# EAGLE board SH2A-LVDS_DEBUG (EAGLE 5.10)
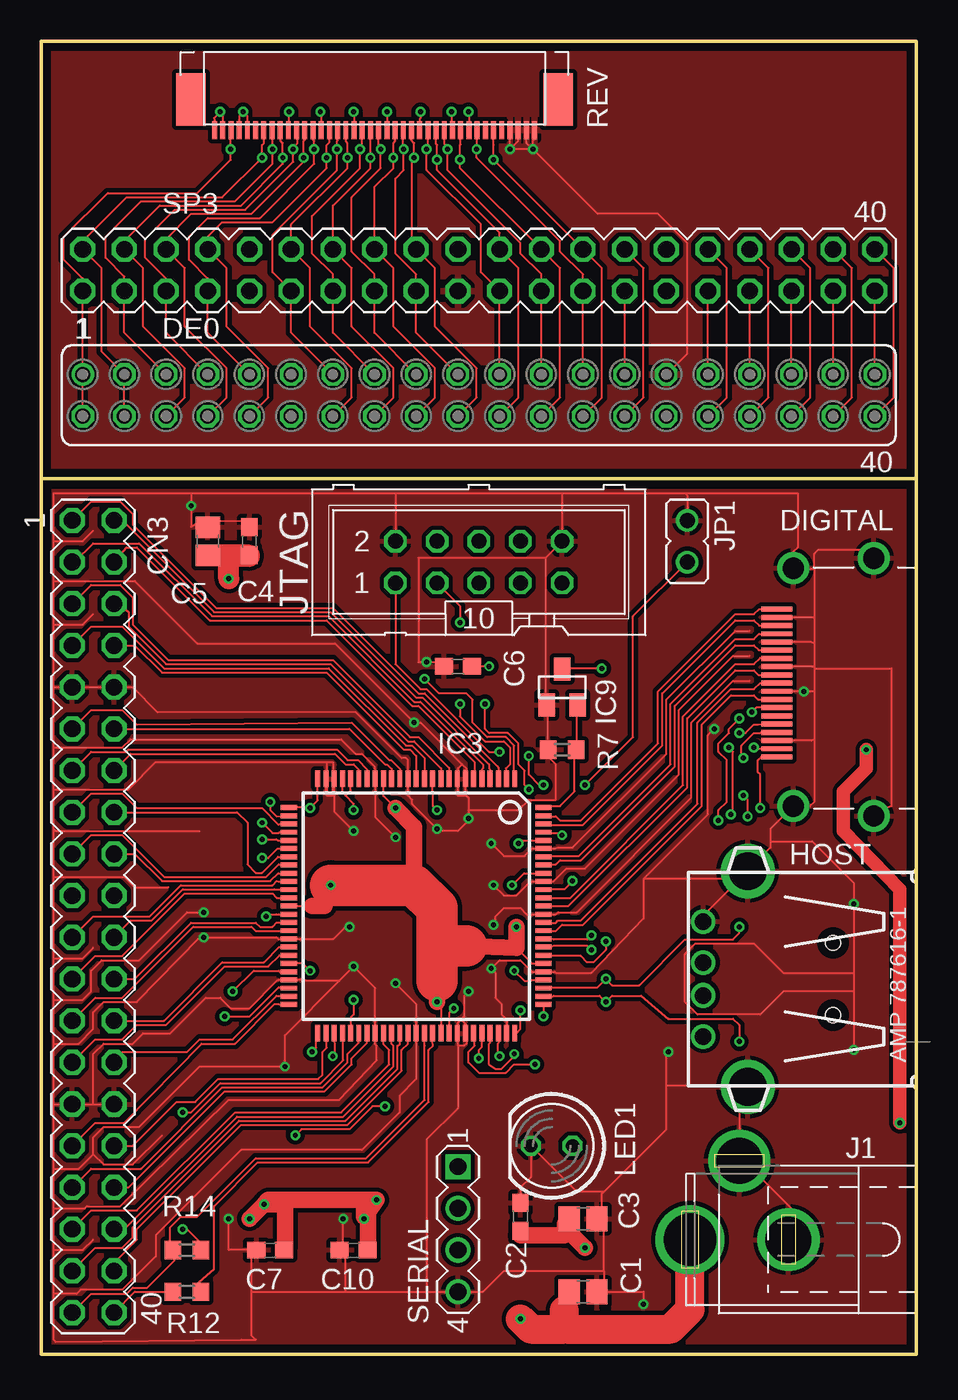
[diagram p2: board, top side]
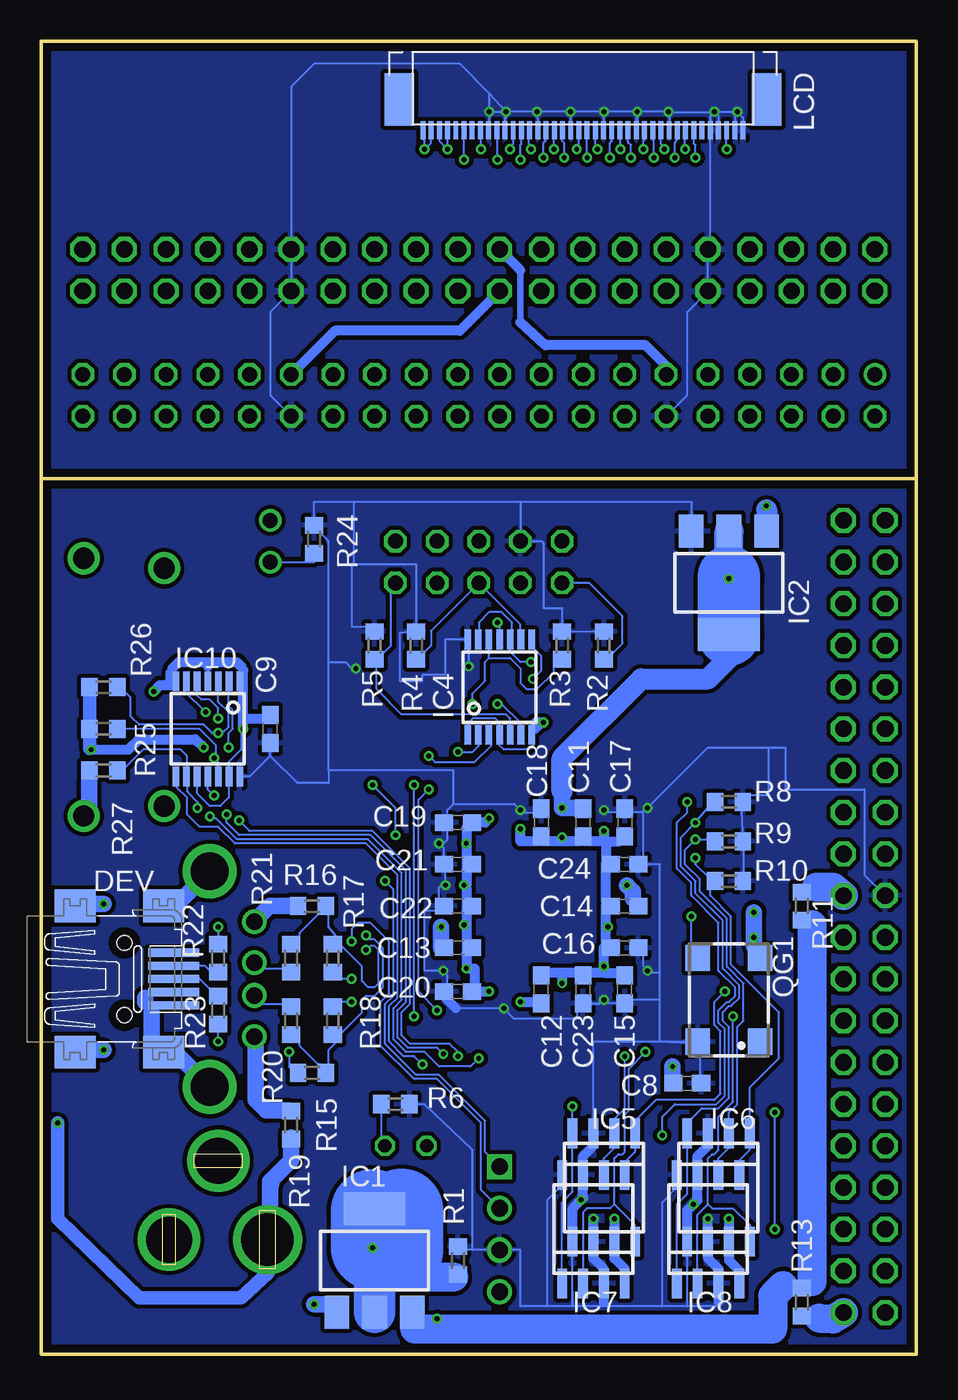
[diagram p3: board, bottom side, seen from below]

Size 53.34 x 80 mm. Coordinates in mm from the lower left corner, seen from the top.
Outline: 0,53.34 0,80 53.34,80 53.34,53.34
Outline: 0,53.34 0,0 53.34,0 53.34,53.34
Outline: 0,53.34 53.34,53.34
Copper layers (1*16): Top 0.035mm / dielectric 1.53mm / Bottom 0.035mm
Design rules "pban_5mil-l2 *": minimum track width 5mil, minimum drill 0.3mm, track to track 5mil, track to pad 0.229mm, pad to pad 5mil, via to via 5mil, smd to smd 5mil, copper to edge 0.5mm, drill to drill 0.5mm, minimum pad ring 0.15mm, minimum via ring 0.15mm, stop-mask expansion 4mil, vias tented up to drill 0.35mm, thermal gap 10mil

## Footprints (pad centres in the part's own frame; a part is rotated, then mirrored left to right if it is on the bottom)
C2012 = smd 1.3 x 1.5: 1 -0.85,0; 2 0.85,0
C1608 = smd 1.1 x 1: 1 -0.85,0; 2 0.85,0
MA20-2 = drill 1.016 octagon: 1 -24.13,-1.27; 2 -24.13,1.27; 3 -21.59,-1.27; 4 -21.59,1.27; 5 -19.05,-1.27; 6 -19.05,1.27; 7 -16.51,-1.27; 8 -16.51,1.27; 9 -13.97,-1.27; 10 -13.97,1.27; 11 -11.43,-1.27; 12 -11.43,1.27; 13 -8.89,-1.27; 14 -8.89,1.27; 15 -6.35,-1.27; 16 -6.35,1.27; 17 -3.81,-1.27; 18 -3.81,1.27; 19 -1.27,-1.27; 20 -1.27,1.27; 21 1.27,-1.27; 22 1.27,1.27; 23 3.81,-1.27; 24 3.81,1.27; 25 6.35,-1.27; 26 6.35,1.27; 27 8.89,-1.27; 28 8.89,1.27; 29 11.43,-1.27; 30 11.43,1.27; 31 13.97,-1.27; 32 13.97,1.27; 33 16.51,-1.27; 34 16.51,1.27; 35 19.05,-1.27; 36 19.05,1.27; 37 21.59,-1.27; 38 21.59,1.27; 39 24.13,-1.27; 40 24.13,1.27
FE20-2 = drill 0.914 round: 1 -24.13,1.27 | drill 0.914 octagon: 2 -24.13,-1.27; 3 -21.59,1.27; 4 -21.59,-1.27; 5 -19.05,1.27; 6 -19.05,-1.27; 7 -16.51,1.27; 8 -16.51,-1.27; 9 -13.97,1.27; 10 -13.97,-1.27; 11 -11.43,1.27; 12 -11.43,-1.27; 13 -8.89,1.27; 14 -8.89,-1.27; 15 -6.35,1.27; 16 -6.35,-1.27; 17 -3.81,1.27; 18 -3.81,-1.27; 19 -1.27,1.27; 20 -1.27,-1.27; 21 1.27,1.27; 22 1.27,-1.27; 23 3.81,1.27; 24 3.81,-1.27; 25 6.35,1.27; 26 6.35,-1.27; 27 8.89,1.27; 28 8.89,-1.27; 29 11.43,1.27; 30 11.43,-1.27; 31 13.97,1.27; 32 13.97,-1.27; 33 16.51,1.27; 34 16.51,-1.27; 35 19.05,1.27; 36 19.05,-1.27; 37 21.59,1.27; 38 21.59,-1.27; 39 24.13,1.27; 40 24.13,-1.27
32005-201A = smd 3.1 x 0.5: 1 3,1.6; 2 3,0.8; 3 3,0; 4 3,-0.8; 5 3,-1.6 | smd 2.5 x 2: M1 -3,-4.45; M2 -3,4.45; M3 2.4,4.45; M4 2.4,-4.45 | hole 0.9: 0,2.2; 0,-2.2
HDMI-FCI-A-UPDATE = smd 0.3 x 1.9: 1 4.75,8.5; 2 4.25,8.5; 3 3.75,8.5; 4 3.25,8.5; 5 2.75,8.5; 6 2.25,8.5; 7 1.75,8.5; 8 1.25,8.5; 9 0.75,8.5; 10 0.25,8.5; 11 -0.25,8.5; 12 -0.75,8.5; 13 -1.25,8.5; 14 -1.75,8.5; 15 -2.25,8.5; 16 -2.75,8.5; 17 -3.25,8.5; 18 -3.75,8.5; 19 -4.25,8.5 | drill 1.3 round: 20 -7.85,2.6; 21 7.85,2.6; 22 -7.25,7.5; 23 7.25,7.5
USB = drill 1 round: 1 -3.5,12.99; 2 -1,12.99; 3 1,12.99; 4 3.5,12.99 | drill 2.3 round: P$1 -6.57,10.28; P$2 6.57,10.28
SOT223 = smd 1.5 x 2: 1 -2.3,-3.15; 2 0,-3.15; 3 2.3,-3.15 | smd 3.8 x 2: 4 0,3.15
VQ100 = smd 1 x 0.3: 1 -7.75,6; 2 -7.75,5.5; 3 -7.75,5; 4 -7.75,4.5; 5 -7.75,4; 6 -7.75,3.5; 7 -7.75,3; 8 -7.75,2.5; 9 -7.75,2; 10 -7.75,1.5; 11 -7.75,1; 12 -7.75,0.5; 13 -7.75,0; 14 -7.75,-0.5; 15 -7.75,-1; 16 -7.75,-1.5; 17 -7.75,-2; 18 -7.75,-2.5; 19 -7.75,-3; 20 -7.75,-3.5; 21 -7.75,-4; 22 -7.75,-4.5; 23 -7.75,-5; 24 -7.75,-5.5; 25 -7.75,-6; 51 7.75,-6; 52 7.75,-5.5; 53 7.75,-5; 54 7.75,-4.5; 55 7.75,-4; 56 7.75,-3.5; 57 7.75,-3; 58 7.75,-2.5; 59 7.75,-2; 60 7.75,-1.5; 61 7.75,-1; 62 7.75,-0.5; 63 7.75,0; 64 7.75,0.5; 65 7.75,1; 66 7.75,1.5; 67 7.75,2; 68 7.75,2.5; 69 7.75,3; 70 7.75,3.5; 71 7.75,4; 72 7.75,4.5; 73 7.75,5; 74 7.75,5.5; 75 7.75,6 | smd 0.3 x 1: 26 -6,-7.75; 27 -5.5,-7.75; 28 -5,-7.75; 29 -4.5,-7.75; 30 -4,-7.75; 31 -3.5,-7.75; 32 -3,-7.75; 33 -2.5,-7.75; 34 -2,-7.75; 35 -1.5,-7.75; 36 -1,-7.75; 37 -0.5,-7.75; 38 0,-7.75; 39 0.5,-7.75; 40 1,-7.75; 41 1.5,-7.75; 42 2,-7.75; 43 2.5,-7.75; 44 3,-7.75; 45 3.5,-7.75; 46 4,-7.75; 47 4.5,-7.75; 48 5,-7.75; 49 5.5,-7.75; 50 6,-7.75; 76 6,7.75; 77 5.5,7.75; 78 5,7.75; 79 4.5,7.75; 80 4,7.75; 81 3.5,7.75; 82 3,7.75; 83 2.5,7.75; 84 2,7.75; 85 1.5,7.75; 86 1,7.75; 87 0.5,7.75; 88 0,7.75; 89 -0.5,7.75; 90 -1,7.75; 91 -1.5,7.75; 92 -2,7.75; 93 -2.5,7.75; 94 -3,7.75; 95 -3.5,7.75; 96 -4,7.75; 97 -4.5,7.75; 98 -5,7.75; 99 -5.5,7.75; 100 -6,7.75
PW_R-PDSO-G14 = smd 0.4 x 1.2: 1 -1.95,-2.9; 2 -1.3,-2.9; 3 -0.65,-2.9; 4 0,-2.9; 5 0.65,-2.9; 6 1.3,-2.9; 7 1.95,-2.9; 8 1.95,2.9; 9 1.3,2.9; 10 0.65,2.9; 11 0,2.9; 12 -0.65,2.9; 13 -1.3,2.9; 14 -1.95,2.9
AT45DB = smd 0.6 x 1.8: 1 -1.905,-3.3; 2 -0.635,-3.3; 3 0.635,-3.3; 4 1.905,-3.3; 5 1.905,3.3; 6 0.635,3.3; 7 -0.635,3.3; 8 -1.905,3.3
SOT23 = smd 1 x 1.4: 1 -0.95,-1.1; 2 0.95,-1.1; 3 0,1.1
SPC4077A = drill 2.8 round: 1 -3,0; 2 0,-4.8 | drill 3.2 round: 3 3,0
JP1A = drill 0.914 round: 1 0,-1.27; 2 0,1.27
ML10 = drill 0.914 octagon: 1 -5.08,-1.27; 2 -5.08,1.27; 3 -2.54,-1.27; 4 -2.54,1.27; 5 0,-1.27; 6 0,1.27; 7 2.54,-1.27; 8 2.54,1.27; 9 5.08,-1.27; 10 5.08,1.27
FFC-40-0.5B-TYCO = smd 1.1 x 0.3: 1 -0.35,9.75; 2 -0.35,9.25; 3 -0.35,8.75; 4 -0.35,8.25; 5 -0.35,7.75; 6 -0.35,7.25; 7 -0.35,6.75; 8 -0.35,6.25; 9 -0.35,5.75; 10 -0.35,5.25; 11 -0.35,4.75; 12 -0.35,4.25; 13 -0.35,3.75; 14 -0.35,3.25; 15 -0.35,2.75; 16 -0.35,2.25; 17 -0.35,1.75; 18 -0.35,1.25; 19 -0.35,0.75; 20 -0.35,0.25; 21 -0.35,-0.25; 22 -0.35,-0.75; 23 -0.35,-1.25; 24 -0.35,-1.75; 25 -0.35,-2.25; 26 -0.35,-2.75; 27 -0.35,-3.25; 28 -0.35,-3.75; 29 -0.35,-4.25; 30 -0.35,-4.75; 31 -0.35,-5.25; 32 -0.35,-5.75; 33 -0.35,-6.25; 34 -0.35,-6.75; 35 -0.35,-7.25; 36 -0.35,-7.75; 37 -0.35,-8.25; 38 -0.35,-8.75; 39 -0.35,-9.25; 40 -0.35,-9.75 | smd 3.2 x 1.8: P$41 1.5,11.2; P$42 1.5,-11.2
LED5MM = drill 0.813 octagon: A -1.27,0; K 1.27,0
SM77H = smd 1.6 x 1.5: 1 -2.55,-1.9; 2 2.55,-1.9; 3 2.55,1.9; 4 -2.55,1.9
R0603 = smd 1 x 1.1: 1 -0.85,0; 2 0.85,0
MA04-1A = drill 1.016 square: 1 -3.81,0 | drill 1.016 round: 2 -1.27,0; 3 1.27,0; 4 3.81,0

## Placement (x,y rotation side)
C1  10u  [C2012]  33.02,3.81 0 top
C2  0.1u  [C1608]  29.21,8.38 90 top
C3  10u  [C2012]  33.02,8.26 0 top
C4  0.1u  [C1608]  12.7,49.53 90 top
C5  10u  [C2012]  10.16,49.53 90 top
C6  0.1u  [C1608]  25.4,41.91 180 top
C7  0.1u  [C1608]  13.97,6.35 180 top
C8  0.1u  [C1608]  13.97,16.51 180 bottom
C9  0.1u  [C1608]  39.37,38.1 90 bottom
C10  0.1u  [C1608]  19.05,6.35 180 top
C11  0.1u  [C1608]  20.32,32.38 270 bottom
C12  0.1u  [C1608]  22.86,22.23 90 bottom
C13  0.1u  [C1608]  27.94,24.77 0 bottom
C14  0.1u  [C1608]  17.78,27.3 180 bottom
C15  0.1u  [C1608]  17.78,22.23 90 bottom
C16  0.1u  [C1608]  17.78,24.77 180 bottom
C17  0.1u  [C1608]  17.78,32.38 270 bottom
C18  0.1u  [C1608]  22.86,32.38 270 bottom
C19  0.1u  [C1608]  27.94,32.38 0 bottom
C20  0.1u  [C1608]  27.94,22.1 0 bottom
C21  0.1u  [C1608]  27.94,29.84 0 bottom
C22  0.1u  [C1608]  27.94,27.3 0 bottom
C23  0.1u  [C1608]  20.32,22.23 90 bottom
C24  0.1u  [C1608]  17.78,29.84 180 bottom
CN3  [MA20-2]  3.17,26.67 270 top
DE0  [FE20-2]  26.67,58.42 0 top
DEV  MINI-USB-SHELD-32005-201A  [32005-201A]  48.26,22.86 0 bottom
DIGITAL  [HDMI-FCI-A-UPDATE]  53.34,40.64 90 top
HOST  [USB]  53.34,22.86 90 top
IC1  LD117AS33TR-A  [SOT223]  33.02,5.71 0 bottom
IC2  LD117AS12TR-A  [SOT223]  11.43,46.99 180 bottom
IC3  XC3S200AVQ100  [VQ100]  22.86,27.3 270 top
IC4  74VHC125TSSOP  [PW_R-PDSO-G14]  25.4,40.64 0 bottom
IC5  AT45DB081  [AT45DB]  19.05,10.16 180 bottom
IC6  AT45DB081  [AT45DB]  12.06,10.16 180 bottom
IC7  M25P  [AT45DB]  19.68,7.62 0 bottom
IC8  M25P  [AT45DB]  12.7,7.62 0 bottom
IC9  TCM809R(3.3V)  [SOT23]  31.75,40.64 0 top
IC10  74CBT3125TSSOP  [PW_R-PDSO-G14]  43.18,38.1 180 bottom
J1  [SPC4077A]  42.55,6.99 180 top
JP1  [JP1A]  39.37,49.53 180 top
JTAG  [ML10]  26.67,48.26 0 top
LCD  FFC-40TYCO-0.5B  [FFC-40-0.5B-TYCO]  20.32,74.93 90 bottom
LED1  [LED5MM]  31.11,12.7 180 top
QG1  27MHz  [SM77H]  11.43,21.59 90 bottom
R1  0  [R0603]  27.94,5.71 90 bottom
R2  4.7k  [R0603]  19.05,43.18 90 bottom
R3  4.7k  [R0603]  21.59,43.18 90 bottom
R4  4.7k  [R0603]  30.48,43.18 90 bottom
R5  4.7k  [R0603]  33.02,43.18 90 bottom
R6  220  [R0603]  31.75,15.24 0 bottom
R7  4.7k  [R0603]  31.75,36.83 180 top
R8  4.7k  [R0603]  11.43,33.66 0 bottom
R9  4.7k  [R0603]  11.43,31.24 0 bottom
R10  4.7k  [R0603]  11.43,28.83 0 bottom
R11  0  [R0603]  6.99,27.3 270 bottom
R12  0  [R0603]  8.89,3.81 0 top
R13  0  [R0603]  6.99,3.17 90 bottom
R14  220  [R0603]  8.89,6.35 0 top
R15  15k  [R0603]  36.83,17.14 0 bottom
R16  15k  [R0603]  36.83,27.3 0 bottom
R17  1.5k  [R0603]  35.56,24.13 270 bottom
R18  1.5k  [R0603]  35.56,20.32 90 bottom
R19  0  [R0603]  38.1,13.97 90 bottom
R20  22  [R0603]  38.1,20.32 90 bottom
R21  22  [R0603]  38.1,24.13 270 bottom
R22  22  [R0603]  42.55,24.13 270 bottom
R23  22  [R0603]  42.55,20.95 90 bottom
R24  4.7k  [R0603]  36.7,49.66 270 bottom
R25  10k  [R0603]  49.53,38.1 180 bottom
R26  10k  [R0603]  49.53,40.64 180 bottom
R27  10k  [R0603]  49.53,35.56 0 bottom
REV  FFC-40TYCO-0.5B  [FFC-40-0.5B-TYCO]  20.32,74.93 90 top
SERIAL  [MA04-1A]  25.4,7.62 270 top
SP3  [MA20-2]  26.67,66.04 0 top

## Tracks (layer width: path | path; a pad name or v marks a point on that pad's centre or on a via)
CCLK  (via drill 0.3)
  Top 0.127: v17.78,18.16 17.91,18.29 17.91,18.8 IC3.53
  Bottom 0.127: IC7.6 19.05,11.94 18.41,12.57 IC5.2 18.41,14.35 17.78,14.99 v17.78,18.16
CEC1  (via drill 0.3)
  Top 0.127: DIGITAL.13 43.58,39.39 v43.31,39.12
  Bottom 0.127: v43.31,39.12 44.58,40.39 44.58,40.9 IC10.6
CH0N
  Top 0.127: DIGITAL.9 43.7,41.39 43.43,41.66 42.29,41.66 39.37,38.73 39.37,34.54 32.13,27.3 IC3.88
CH0P
  Top 0.127: DIGITAL.7 43.97,42.39 43.81,42.42 43.43,42.04 42.29,42.04 39.12,38.86 39.12,34.67 32.26,27.81 30.62,27.81 IC3.89
CH1N
  Top 0.127: DIGITAL.6 43.72,42.89 43.43,43.18 42.29,43.18 38.61,39.5 38.61,35.81 32.89,30.1 31.62,30.1 31.37,29.84 30.65,29.84 IC3.93
CH1P
  Top 0.127: DIGITAL.4 43.74,43.89 43.43,43.56 42.29,43.56 38.35,39.62 38.35,35.94 32.77,30.35 30.69,30.35 IC3.94
CH2N
  Top 0.127: DIGITAL.3 43.76,44.39 43.43,44.7 42.29,44.7 37.85,40.26 37.85,37.08 33.02,32.26 30.66,32.26 IC3.98
CH2P
  Top 0.127: DIGITAL.1 43.76,45.39 43.43,45.09 42.29,45.09 37.59,40.39 37.59,37.21 32.89,32.51 31.62,32.51 31.37,32.77 30.65,32.77 IC3.99
CH3N
  Top 0.127: DIGITAL.12 43.68,39.89 43.43,40.13 42.04,40.13 40.26,38.35 40.26,33.4 33.02,26.16 31.75,26.16 31.37,25.78 30.63,25.78 IC3.85
CH3P
  Top 0.127: DIGITAL.10 43.82,40.89 43.43,40.51 42.04,40.51 40.01,38.48 40.01,33.53 32.89,26.42 31.5,26.42 31.37,26.29 30.63,26.29 IC3.86
CH4  (via drill 0.3)
  Top 0.127: v42.55,38.73 41.91,38.1 41.91,37.85 41.27,37.21 41.27,36.7 41.78,36.2 41.78,33.66 41.27,33.15 v41.27,32.51 | v27.94,18.16 27.81,18.29 27.81,18.92 27.86,18.97 IC3.73
  Bottom 0.127: IC10.5 43.83,40.15 43.56,39.88 43.05,39.88 42.55,39.37 v42.55,38.73 | v41.27,32.51 40.64,31.88 33.15,31.88 30.86,29.59 30.86,21.34 31.37,20.83 31.37,19.43 30.86,18.92 28.45,18.92 27.94,18.41 v27.94,18.16
CH5  (via drill 0.3)
  Top 0.127: 27.3,19.43 IC3.72 27.36,18.98 27.3,18.92 27.3,17.65 27.69,17.4 28.07,17.4 28.83,18.16 v28.83,18.29 | v42.04,32.89 42.16,33.02 42.16,36.7 v41.91,36.96
  Bottom 0.127: v41.91,36.96 41.91,37.85 41.66,38.1 41.66,39.24 41.91,39.5 41.91,41.02 IC10.2 | v42.04,32.89 42.04,32.38 41.27,31.62 33.27,31.62 31.11,29.46 31.11,21.46 31.62,20.95 31.62,19.3 30.99,18.67 29.21,18.67 v28.83,18.29
CH6  (via drill 0.3)
  Top 0.127: v43.05,32.77 43.05,33.78 v42.8,34.04 | v26.67,18.03 26.67,18.54 26.86,18.73 IC3.71
  Bottom 0.127: 43.18,35.31 IC10.11 43.18,34.42 v42.8,34.04 | v43.05,32.77 42.93,32.64 42.67,32.64 41.4,31.37 33.4,31.37 31.37,29.34 31.37,21.59 31.88,21.08 31.88,19.18 31.11,18.41 29.97,18.41 29.08,17.53 27.18,17.53 v26.67,18.03
CH7  (via drill 0.3)
  Top 0.127: v30.1,17.65 28.83,17.65 28.32,17.14 26.67,17.14 26.04,17.78 26.04,18.41 26.42,18.8 26.42,19.43 IC3.70
  Bottom 0.127: v30.1,17.65 30.61,18.16 31.24,18.16 32.13,19.05 32.13,21.21 31.62,21.72 31.62,29.21 33.53,31.11 41.53,31.11 42.55,32.13 43.69,32.13 44.45,32.89 44.45,33.91 45.09,34.54 45.09,35.18 IC10.8
CH8N  (via drill 0.3)
  Top 0.127: IC3.84 30.96,25.3 31.24,25.27 33.27,25.27 v33.53,25.53
  Bottom 0.127: v33.53,25.53 33.27,25.27 33.02,25.27 32.51,24.77 32.51,22.35 33.02,21.84 33.53,21.84 33.78,21.59 33.78,20.83 35.18,19.43 35.56,19.56 35.52,19.43 R18.1 | R18.1 35.56,19.3 | 35.81,17.14 36.2,17.14 36.32,17.65 36.45,17.65 37.59,18.8 37.59,19.05 37.68,19.43 R20.1 | R15.2 35.94,17.14 35.81,17.02 35.81,17.14 | 35.81,17.14 35.81,18.54 35.31,19.05 35.31,19.22 R18.1
CH8P  (via drill 0.3)
  Top 0.127: IC3.83 31.07,24.8 31.24,24.89 33.27,24.89 v33.53,24.64
  Bottom 0.127: v33.53,24.64 33.27,24.89 33.02,24.89 32.77,24.64 32.77,22.61 33.02,22.35 33.4,22.35 33.78,22.73 33.78,23.62 35.18,25.02 | 35.18,25.02 35.56,24.89 35.56,24.64 35.6,24.77 R17.1 | R17.1 35.56,25.15 | 35.81,27.3 36.2,27.3 36.2,26.8 36.45,26.8 37.59,25.65 37.72,25.15 37.93,25.15 R21.1 | R16.2 35.98,27.47 35.81,27.43 35.81,27.3 | 35.18,25.02 35.18,25.27 35.81,26.04 35.81,27.3 | 35.18,25.02 R17.1
CH9N  (via drill 0.3)
  Top 0.127: v42.55,26.04 42.55,25.65 42.16,25.27 39.24,25.27 36.45,22.48 34.8,22.48 v34.42,22.86 33.91,22.35 31.11,22.35 31.07,22.3 IC3.78
  Bottom 0.127: v42.55,26.04 R22.1 | v34.42,22.86 35.31,22.86 35.52,22.99 R17.2
CH9P  (via drill 0.3)
  Top 0.127: IC3.77 31.2,21.8 31.24,21.84 34.04,21.84 v34.42,21.46 34.8,21.84 36.58,21.84 38.23,20.45 42.16,20.45 42.55,20.07 v42.55,19.05
  Bottom 0.127: v34.42,21.46 35.47,21.46 R18.2 | v42.55,19.05 R23.1
CN3_0
  Top 0.127: CN3.1 3.05,51.94 4.83,51.94 5.59,51.18 5.59,50.55 10.67,45.47 17.78,45.47 22.99,40.26 23.37,40.26 27.81,35.81 27.86,35.73 IC3.3
CN3_1
  Top 0.127: CN3.2 4.7,50.55 5.21,50.55 10.54,45.21 17.65,45.21 22.86,40.01 23.24,40.01 27.3,35.94 27.3,35.69 27.36,35.62 IC3.4
CN3_2
  Top 0.127: CN3.3 2.03,48.26 3.17,49.4 5.97,49.4 10.41,44.96 17.53,44.96 22.73,39.75 23.11,39.75 26.92,35.94 26.92,35.69 26.86,35.62 IC3.5
CN3_3
  Top 0.127: CN3.4 5.21,49.15 5.84,49.15 10.29,44.7 17.4,44.7 22.61,39.5 22.99,39.5 26.42,36.07 26.42,35.56 26.36,35.5 IC3.6
CN3_3V3  (via drill 0.3)
  Top 0.127: IC3.92 29.43,29.3 v28.7,28.57 | IC3.96 29.27,31.3 v29.08,31.11 | IC3.55 18.86,20.51 19.05,20.7 v19.05,21.59 | IC3.67 24.86,20.8 v25.15,21.08 | IC3.79 29.92,22.8 29.84,22.73 29.46,22.73 v28.83,23.37 | IC3.11 23.86,34.31 23.88,34.29 23.88,33.4 v24.13,33.15 | IC3.26 16.35,33.3 v16.38,33.27 16.86,33.75 IC3.25 | IC3.22 18.36,34.22 18.54,34.04 | 18.54,34.04 19.05,33.53 v19.05,33.15 | IC3.21 18.86,34.35 18.54,34.04 | IC3.45 15.95,23.8 v16.38,23.37 | 19.94,6.35 C10.1 | 14.86,6.39 C7.1 | v27.3,41.91 C6.1 | IC9.3 31.71,41.99 32,41.78 v34.16,41.78
  Top 1.016: 19.94,6.35 19.94,8.64 v20.45,9.4 19.68,9.4 | v13.59,9.14 14.86,9.14 14.86,6.39 | v12.7,8.26 v13.59,9.14 | v13.59,9.14 13.84,9.4 19.68,9.4 | 19.68,9.4 19.68,8.38
  Bottom 0.127: IC10.14 40.62,35.2 39.37,36.45 | 39.37,36.45 C9.1 | 28.57,32.17 28.57,31.37 28.83,31.11 v29.08,31.11 28.79,30.82 C21.1 28.7,29.76 v28.7,28.57 28.96,28.57 29.08,28.45 29.08,27.6 C22.1 28.83,27.3 29.08,27.05 29.97,27.05 29.97,23.37 v28.83,23.37 28.57,23.11 28.57,21.88 C20.1 | 28.57,32.17 C19.1 | v19.05,21.59 19.3,21.34 19.56,21.34 | 19.56,21.34 20.28,21.34 C23.1 20.32,21.21 20.7,20.83 20.7,20.45 24.51,20.45 v25.15,21.08 28.07,21.08 | C18.1 23.07,33.02 23.88,33.02 24,33.15 v24.13,33.15 24.51,33.53 28.19,33.53 | v16.38,33.27 16.51,33.27 16.76,33.02 17.57,33.02 C17.1 18,33.02 18.8,33.02 18.92,33.15 v19.05,33.15 | C16.1 16.64,24.47 16.64,23.62 v16.38,23.37 16.26,23.24 15.62,23.24 | 16.64,29.84 C24.1 | 15.62,23.24 15.62,29.84 16.64,29.84 | 16.64,29.84 16.64,33.02 v16.38,33.27 | 28.57,32.17 28.57,33.15 28.19,33.53 | 19.56,21.34 19.52,21.38 C15.1 17.74,21.63 17.78,21.59 15.62,21.59 | IC2.3 13.73,51.93 13.72,51.94 24.13,51.94 | 24.13,51.94 JTAG.4 22.86,49.53 22.73,49.4 22.73,45.47 21.59,45.47 21.59,44.07 | 34.29,51.94 36.7,51.94 R24.1 36.7,50.42 35.81,49.53 35.81,42.16 | 34.29,51.94 24.13,51.94 | 10.67,28.32 10.67,28.7 10.41,28.7 10.54,28.96 R10.2 10.54,29 10.54,31.24 R9.2 10.67,33.06 10.67,33.53 10.79,33.66 | CN3.19 3.17,29.21 3.17,34.42 8,34.42 8,36.96 9.02,36.96 | 10.79,33.95 10.88,33.95 10.79,34.04 | 10.79,33.95 R8.2 10.79,33.66 | 12.7,19.05 12.69,18.91 15.62,19.05 | 13.21,19.05 13.21,16.51 C8.1 | 12.7,19.05 QG1.4 12.7,18.29 | 15.62,19.05 13.21,19.05 | 13.21,19.05 12.7,19.05 | 15.62,19.05 19.68,19.05 IC5.3 19.68,12.7 | 15.62,19.05 15.62,21.59 | 15.62,21.59 15.62,23.24
  Bottom 0.127: 10.79,34.04 10.79,33.95 | 10.79,33.95 10.79,33.66 | 9.02,36.96 12.7,36.96 v16.38,33.27 | 9.02,36.96 9.02,34.04 10.79,34.04 | R1.2 27.94,6.35 27.05,6.35 | 27.05,6.35 SERIAL.3 24.13,6.35 24.13,2.92 22.48,2.92 | 20.95,3.81 IC5.5 | 20.95,3.81 20.95,2.92 19.05,2.92 | 12.7,12.7 IC6.3 | IC8.3 12.06,5.21 | IC7.3 19.05,5.21 | 13.97,2.92 IC6.5 | 12.06,3.17 12.06,2.92 13.97,2.92 | 13.97,2.92 15.49,2.92 | 19.05,2.92 19.05,3.17 | 22.48,2.92 20.96,2.92 20.95,3.81 | IC8.8 14.61,10.16 15.49,9.27 15.49,2.92 | 15.49,2.92 19.05,2.92 | IC7.8 21.59,10.29 22.48,9.4 22.48,2.92 | 27.3,43.56 v27.3,41.91 | 27.3,43.56 IC4.14 | 34.29,48.13 30.48,48.13 R4.2 31.5,43.94 31.5,41.02 30.1,41.02 30.1,41.4 28.7,41.4 28.7,43.56 27.3,43.56 | 34.29,48.13 34.42,48.13 34.42,44.32 33.02,44.32 R5.2 | 21.72,44.07 21.46,43.94 | 21.59,44.07 21.72,44.07 | 21.59,44.07 21.46,44.07 R2.2 | 21.59,44.07 21.46,43.94 | 21.46,43.94 21.34,43.94 | 34.29,51.94 34.29,48.13 | 39.37,36.45 37.72,34.8 35.81,34.8 35.81,35.56 | 35.81,35.56 28.19,35.56 28.19,33.53 | 27.05,6.35 27.05,12.45 29.97,15.24 R6.2 | 35.81,35.56 35.81,42.16 | R3.2 21.72,43.98 21.72,44.07 | v34.16,41.78 34.42,41.78 34.8,42.16 35.81,42.16
  Bottom 0.61: 28.07,21.08 28.57,21.59 28.57,21.88 | IC5.5 20.95,8.89 v20.45,9.4 20.32,9.53 IC7.7 20.32,12.06 19.68,12.7 | IC6.5 13.97,8.76 v13.59,9.14 13.34,9.4 IC8.7 13.34,12.06 12.7,12.7 | 12.06,5.21 12.7,5.84 IC6.6 v12.7,8.26 | 19.05,5.21 19.68,5.84 IC5.6 v19.68,8.26 | IC8.3 12.06,3.17 | 19.05,3.17 IC7.3
  pour Bottom (isolate 0.254): 0.64,0.64 52.7,0.64 52.7,52.7 0.64,52.7
CN3_4
  Top 0.127: CN3.5 3.05,46.86 4.83,46.86 5.59,46.1 5.59,44.45 7.75,42.29 17.78,42.29 22.48,37.59 22.99,37.59 24.86,35.72 IC3.9
CN3_5
  Top 0.127: CN3.6 4.7,45.72 5.33,45.21 5.33,44.32 7.62,42.04 17.65,42.04 22.35,37.34 22.73,37.34 24.38,35.69 24.38,35.05 IC3.10
CN3_5V  (via drill 0.3)
  Top 0.127: DIGITAL.18 43.5,36.89 v43.43,36.96 | C1.1 32.13,3.01 31.88,2.67 32,1.52
  Top 0.813: v52.32,14.1 52.32,28.32 48.9,31.88 48.9,34.29 50.29,35.69 v50.29,36.83
  Top 1.778: v29.21,2.16 29.84,1.52 31.88,1.52 31.88,2.67 | J1.3 39.55,2.71 38.35,1.52 32,1.52
  Bottom 0.127: v50.29,36.83 50.38,36.92 50.47,36.83 | 6.35,26.16 R11.2 | 6.35,4.45 R13.2 7.53,4.03 8.13,4.19 | 30.57,1.52 IC1.3 30.5,1.8 v29.21,2.16 | 38.1,13.21 38.39,13.04 R19.1 38.39,12.91 39.5,7.24 | J1.3 39.37,7.16
  Bottom 0.61: v43.43,36.96 43.94,37.47 47.37,37.47 48.01,36.83 v50.29,36.83
  Bottom 0.813: R26.2 R25.2 50.38,36.92 | 39.5,7.24 39.5,4.95 41.15,3.43 47.37,3.43 52.32,8.26 v52.32,14.1
  Bottom 1.016: 38.1,13.21 38.1,11.81 39.37,10.54 39.37,7.16
  Bottom 1.778: 6.35,4.45 6.35,26.16 | 8.13,4.19 8.76,3.56 8.76,1.52 30.57,1.52
CN3_6
  Top 0.127: IC3.12 23.36,34.93 | CN3.7 3.05,44.32 4.95,44.32 7.49,41.78 17.53,41.78 22.23,37.08 22.61,37.08 23.37,36.32 IC3.12 | IC3.12 23.37,35.06 | IC3.12 23.37,34.92 | IC3.12
CN3_7
  Top 0.127: CN3.8 5.71,43.18 7.37,41.53 17.4,41.53 22.1,36.83 22.48,36.83 22.86,36.45 IC3.13
CN3_8
  Top 0.127: CN3.11 3.05,39.24 4.95,39.24 5.84,38.35 18.92,38.48 21.21,36.2 21.34,36.2 21.86,35.67 IC3.15
CN3_9
  Top 0.127: CN3.12 18.8,38.1 20.95,35.94 21.08,35.92 21.36,35.66 IC3.16
CN3_10
  Top 0.127: CN3.13 3.05,36.7 5.21,36.7 5.33,36.83 18.03,36.83 18.67,36.2 19.3,36.2 19.86,35.64 IC3.19
CN3_11
  Top 0.127: CN3.14 5.46,36.58 17.91,36.58 18.54,35.94 19.05,35.94 19.36,35.62 IC3.20
CN3_12
  Top 0.127: CN3.15 3.05,34.16 4.95,34.16 5.84,33.27 13.46,33.27 14.48,32.26 14.53,32.3 IC3.28
CN3_13
  Top 0.127: CN3.16 11.94,33.02 12.57,32.38 12.57,29.84 13.08,29.34 13.46,29.34 14.43,30.3 IC3.32
CN3_14
  Top 0.127: CN3.17 3.05,31.62 4.95,31.62 7.49,29.08 13.72,29.08 14.48,29.84 14.64,29.8 IC3.33
CN3_15
  Top 0.127: IC3.34 14.45,29.3 13.97,28.83 7.37,28.83 5.71,30.48 CN3.18
CN3_16
  Top 0.127: CN3.21 3.17,26.67 6.6,26.67 8.51,28.57 14.1,28.57 14.35,28.83 14.45,28.8 IC3.35
CN3_17
  Top 0.127: CN3.22 5.46,26.42 6.73,26.42 8.64,28.32 14.22,28.32 14.37,28.3 IC3.36
CN3_18
  Top 0.127: CN3.23 3.3,24.26 4.95,24.26 8.76,28.07 14.1,28.07 14.36,27.8 IC3.37
CN3_19
  Top 0.127: CN3.24 5.71,22.86 9.14,26.29 13.08,26.29 13.34,26.04 14.1,26.04 14.37,26.3 IC3.40
CN3_20
  Top 0.127: CN3.25 3.3,21.72 4.95,21.72 9.27,26.04 12.83,26.04 13.08,25.78 14.48,25.78 14.88,25.8 IC3.41
CN3_21
  Top 0.127: CN3.26 7.49,20.32 11.05,23.88 13.59,23.88 14.52,24.8 IC3.43
CN3_22
  Top 0.127: CN3.27 3.3,19.18 4.95,19.18 5.84,20.07 7.62,20.07 11.18,23.62 13.84,23.62 14.53,24.3 IC3.44
CN3_23
  Top 0.127: CN3.28 4.45,17.91 4.95,18.41 8.89,18.41 9.65,19.18 11.68,19.18 14.35,21.84 14.61,21.84 14.69,21.8 IC3.49
CN3_24
  Top 0.127: CN3.31 3.3,14.1 5.08,14.1 9.78,18.92 11.81,18.92 14.22,21.34 14.48,21.34 14.51,21.3 IC3.50
CN3_25
  Top 0.127: CN3.32 5.59,12.7 8.26,15.37 9.4,15.37 10.79,16.76 16.89,16.76 17.14,17.02 17.14,18.41 17.4,18.67 17.4,19.05 17.36,19.22 IC3.52
CN3_26
  Top 0.127: CN3.33 3.05,11.3 6.1,11.3 11.05,16.26 17.14,16.26 18.67,17.78 18.67,18.29 19.36,18.98 IC3.56
CN3_27
  Top 0.127: CN3.34 5.33,10.16 11.18,16 17.27,16 18.92,17.65 18.92,18.03 19.86,18.97 IC3.57
CN3_28
  Top 0.127: CN3.35 3.05,8.76 5.84,8.76 11.81,14.73 18.29,14.73 21.21,17.65 21.21,18.54 20.86,18.89 IC3.59
CN3_29
  Top 0.127: CN3.36 5.08,7.62 11.94,14.48 18.41,14.48 21.46,17.53 21.46,18.8 21.36,18.9 IC3.60
CN3_30
  Top 0.127: CN3.37 3.3,6.48 4.95,6.48 5.59,7.11 5.59,7.75 12.06,14.22 18.54,14.22 21.72,17.4 21.72,18.8 21.86,18.91 IC3.61
CN3_31
  Top 0.127: CN3.38 4.45,5.59 5.84,6.99 5.84,7.62 12.19,13.97 18.67,13.97 21.97,17.27 21.97,18.54 22.36,18.91 IC3.62
CN3_32
  Top 0.127: CN3.39 3.05,3.68 5.21,3.68 5.59,4.06 6.48,4.06 8.13,5.71 8.13,6.35 | 7.87,6.22 7.87,6.35 | 7.87,6.22 7.91,6.22 R14.1 | 8.13,6.35 R14.1 | 8.13,6.35 8.26,6.35 | R14.1 7.87,6.22 | R14.1 7.87,6.35 | 7.87,6.35 7.87,7.75 8.51,8.38 9.53,8.38 13.08,11.94 19.81,11.94 23.37,15.49 23.37,18.8 23.36,19.06 IC3.64
CN3_33
  Top 0.127: R12.2 9.4,4.19 10.54,5.21 10.54,9.02 13.21,11.68 19.94,11.68 23.62,15.37 23.62,18.54 23.88,18.8 23.86,19.07 IC3.65
CN3_33P
  Top 0.127: CN3.40 5.71,3.81 7.75,3.81 8.26,3.77 R12.1
  Bottom 0.127: R13.1 5.93,2.2
  Bottom 1.778: 5.93,2.2 5.08,2.16 CN3.40
CN3_CLK  (via drill 0.3)
  Top 0.127: v13.72,26.67 13.84,26.8 14.35,26.8 14.49,26.8 IC3.39
  Bottom 0.127: QG1.3 12.82,23.5 12.83,24 12.83,24.38 13.72,24.51 v13.72,26.67
CN3_GND  (via drill 0.3)
  Top 0.127: DIGITAL.2 47.06,44.89 47.12,44.83 | 47.12,47.88 47.12,44.83 | 47.12,47.88 45.85,47.88 DIGITAL.23 45.84,48.89 46.1,49.15 46.1,52.45 39.24,52.45 | DIGITAL.5 46.91,43.39 47.12,43.31 | 47.12,44.83 47.12,43.31 | 46.97,41.89 DIGITAL.8 | 46.97,41.89 47.12,41.91 47.12,43.31 | DIGITAL.11 46.99,40.39 47.12,40.39 | 46.97,41.89 47.12,41.87 47.12,41.78 | DIGITAL.17 46.94,37.39 47.12,37.47 | 47.12,40.39 47.12,37.47 | 47.12,37.47 47.12,33.66 46.85,33.39 DIGITAL.22 44.45,32 44.45,31.24 | 47.12,40.39 v46.48,40.39 | v38.23,18.41 38.1,18.41 38.1,16.38 | 38.1,16.38 42.29,16.38 | 42.29,16.38 42.97,16.38 HOST.P$1 | HOST.4 40.35,26.72 HOST.P$2 | 42.29,16.38 42.55,16.13 J1.2 42.83,11.79 45.72,8.89 45.72,7.16 J1.1 | v21.59,31.5 20.36,32.73 IC3.18 20.36,35.65 20.32,35.69 20.32,35.81 19.56,36.58 19.18,36.58 18.29,37.47 5.46,37.47 4.95,36.96 0.76,36.96 | v27.43,31.11 28.19,30.35 29.46,30.35 29.92,30.8 IC3.95 31.31,30.8 31.5,30.86 32.38,30.86 38.1,36.58 38.1,39.88 42.29,44.07 43.18,44.07 | v27.56,28.57 28.19,27.94 28.96,27.94 29.82,28.8 IC3.91 31.22,28.8 32,29.59 33.15,29.59 38.86,35.31 38.86,39.24 42.16,42.55 43.18,42.55 | v27.56,26.16 27.69,26.29 27.69,26.67 28.19,27.18 29.21,27.18 29.58,26.8 IC3.87 31.36,26.8 31.37,26.8 31.5,26.92 32.64,26.92 39.62,33.91 39.62,38.48 42.16,41.02 43.18,41.02 | IC3.74 28.36,20.41 28.07,20.7 28.07,21.34 27.69,21.72 27.69,23.24 v27.43,23.5 27.94,24 29.21,24 29.91,23.3 IC3.80 31.3,23.3 31.37,23.24 33.53,23.24 36.7,26.54 36.7,28.96 | IC3.68 25.36,20.15 25.59,20.38 | 25.59,20.38 25.78,20.57 25.78,21.84 v26.04,22.1 | 25.59,20.38 25.86,20.11 IC3.69 25.91,19.51 25.91,18.92 25.78,18.8 25.4,18.8
  Top 0.127: v21.59,22.61 22.86,21.34 IC3.63 22.86,16.76 21.84,15.75 21.84,14.73 19.56,12.45 12.19,12.45 6.99,7.24 6.99,5.97 4.95,3.94 2.41,3.94 2.16,3.68 0.76,3.68 | 18.16,22.73 16,22.73 15.93,22.8 IC3.47 14.48,22.8 14.35,22.73 12.7,21.08 11.56,21.08 10.92,21.72 10.03,21.72 7.87,19.56 6.22,19.56 5.59,18.92 3.81,18.92 3.17,18.29 3.17,15.24 | 18.16,22.73 v19.05,23.62 20.36,22.31 IC3.58 20.36,18.88 20.45,18.8 20.45,17.91 18.16,15.49 11.43,15.49 4.83,9.02 2.79,9.02 2.67,8.89 0.76,8.89 | v18.8,26.04 18.54,26.04 17.81,25.3 IC3.42 14.48,25.27 14.35,25.4 v9.91,25.4 9.65,25.4 5.84,21.46 3.81,21.46 3.17,20.83 3.17,19.81 2.29,18.92 0.76,18.92 | 25.86,34.08 IC3.7 | 25.86,34.08 26.04,33.91 v26.04,32.64 26.04,32.51 25.4,31.88 24.26,31.88 v24.13,32 22.61,33.53 22.61,33.78 22.36,34.03 IC3.14 22.36,35.69 22.35,36.2 22.23,36.32 21.97,36.32 19.18,39.12 7.11,39.11 5.59,40.64 5.59,40.63 CN3.10 | 30.86,37.34 30.86,36.45 31.37,35.94 31.37,33.78 29.72,33.78 29.08,33.15 26.04,33.15 | 25.86,34.08 25.81,34.04 25.4,34.04 25.36,34.08 IC3.8 25.4,35.6 25.4,35.69 25.65,35.94 | 17.86,34.04 17.86,33.07 v19.05,31.88 | 17.86,34.04 IC3.23 17.78,35.31 | IC3.24 17.36,34.12 17.4,34.04 | 17.78,34.04 17.86,34.04 | 17.4,34.04 17.78,34.04 | 17.78,35.43 17.78,36.07 17.4,36.07 | 0.76,40.64 CN3.9 CN3.10 | 3.17,45.09 2.54,44.45 0.76,44.45 | 0.76,40.64 0.76,44.45 | 0.76,44.45 0.76,47.12 | 0.76,47.12 5.71,47.12 9.53,43.31 17.91,43.31 v22.73,38.48 23.11,38.48 25.65,35.94 | 25.65,35.94 25.91,35.69 25.91,35.56 25.78,35.56 25.78,35.43 | C4.2 12.57,50.8 10.03,50.76 C5.2 10.07,50.97 9.14,50.42 v9.14,51.69 9.14,52.45
  Top 0.127: 9.14,52.45 21.59,52.45 | 31.75,52.45 39.24,52.45 | 31.75,52.45 JTAG.10 30.73,48.51 | 21.59,52.45 31.75,52.45 | 21.59,52.45 JTAG.2 | 9.14,52.45 0.76,52.45 0.76,49.53 | 3.17,50.16 2.54,49.53 0.76,49.53 | 0.76,47.12 0.76,49.53 | JP1.1 39.37,52.32 39.24,52.45 | 47.12,47.88 47.12,48.77 47.37,49.02 50.21,49.02 DIGITAL.21 | 47.12,41.78 47.12,40.39 | 47.12,41.78 51.82,41.78 51.82,33.4 50.64,32.89 DIGITAL.20 | v41.02,38.1 40.64,37.72 40.64,32.89 36.7,28.96 | HOST.P$2 42.16,29.46 41.66,28.96 36.7,28.96 | 44.45,31.24 44.45,30.86 43.18,29.59 43.18,29.55 HOST.P$2 | 0.76,18.92 0.76,21.59 | 3.17,24.77 2.54,24.13 0.76,24.13 | 0.76,21.59 0.76,24.13 | 0.76,24.13 0.76,29.08 | 7.75,28.45 5.71,28.45 5.08,29.08 0.76,29.08 | 0.89,31.88 0.76,31.88 | 0.89,31.88 9.65,31.88 | 0.76,29.08 0.76,32 | 0.76,34.42 0.76,36.96 | 0.76,36.96 0.76,40.64 | v36.7,3.05 36.7,3.81 34.29,3.81 | 33.66,3.81 C1.2 34.29,3.81 | 34.29,5.08 34.29,3.81 | 34.29,9.91 34.16,9.78 34.16,8.26 C3.2 34.29,7.83 34.29,5.08 | 34.29,9.91 32.64,9.91 LED1.K 29.84,10.79 29.21,10.16 C2.2 | v18.41,8.26 18.41,6.48 18.2,6.26 C10.2 18.54,6.01 18.54,3.81 | v11.43,8.26 11.43,6.35 12.83,6.35 | 18.54,3.81 SERIAL.4 26.92,3.81 28.19,5.08 34.29,5.08 | 12.83,6.35 C7.2 | 12.83,3.81 12.83,6.35 | 12.83,3.81 18.54,3.81 | R7.2 30.86,36.83 30.86,39.5 IC9.1 30.73,39.62 30.73,48.51 | 3.17,15.24 CN3.30 | 0.76,15.24 CN3.29 3.17,15.24 | 0.76,6.35 0.76,0.89 0.89,0.76 12.19,0.89 13.08,0.89 12.83,1.14 12.83,3.81 | 3.17,6.99 2.54,6.35 0.76,6.35 | 0.76,6.35 0.76,8.89 | 0.76,8.89 0.76,11.3 | 18.16,22.73 14.86,19.43 v14.86,17.53 9.65,17.53 5.97,13.84 3.81,13.84 3.17,13.21 3.17,12.19 | 3.17,12.19 2.29,11.3 0.76,11.3
  Top 0.127: 3.17,12.19 3.81,11.56 5.59,11.56 7.37,13.34 | 0.76,11.3 0.76,15.24 | 0.76,15.24 0.76,18.92 | 30.73,48.51 22.99,48.51 22.99,42.16 v23.5,42.16 24.64,42.16 24.64,42.04 | 34.29,9.91 38.1,13.72 38.1,16.38 | 49.53,22.1 45.21,22.1 43.81,20.7 40.01,20.7 39.24,21.46 39.24,24.38 39.88,25.02 43.43,25.02 45.21,23.24 49.53,23.24 | 49.53,22.1 v49.53,27.43 49.53,28.7 46.99,31.24 44.45,31.24 | 49.53,22.1 v49.53,18.54 | 17.4,36.07 6.99,36.07 5.33,34.42 0.76,34.42 | 17.4,36.07 17.4,34.04 | 17.78,35.43 17.86,35.35 | 0.76,21.59 2.54,21.59 3.05,22.1 3.05,23.37 3.68,24 5.97,24 8.89,26.92 v9.91,26.92 | 17.78,34.04 17.78,35.31 | 17.78,35.43 17.78,35.31 | 25.4,18.8 25.4,19.43 | 25.4,18.8 25.4,14.99 23.5,13.08 23.5,3.81 | 0.76,32 0.76,34.42 | 0.76,32 0.89,31.88
  Bottom 0.127: 45.45,41.51 45.34,41.63 | 45.34,41.63 IC10.7 | IC10.10 43.83,35.45 43.81,34.54 43.81,34.16 43.05,33.4 42.42,33.4 41.91,33.91 41.91,35.3 | 41.91,35.3 IC10.13 | 37.59,17.14 R15.1 38.23,17.53 v38.23,18.41 | 46.66,21.26 DEV.5 | 46.66,21.26 46.99,21.46 | 46.99,21.72 46.7,21.97 DEV.4 | 45.86,18.43 DEV.M4 | 45.86,18.43 46.61,19.18 | 46.61,20.83 46.61,21.18 46.66,21.26 | 46.61,26.42 46.74,26.54 46.74,27.18 46.6,27.31 DEV.M3 45.18,27.31 | 45.2,18.43 45.86,18.43 | 18.92,29.84 C24.2 | 18.92,27.6 C14.2 18.92,27.3 | 18.92,25.06 C16.2 19.05,24.77 | 20.32,23.24 C23.2 20.32,23.11 20.45,23.24 | 22.69,23.24 C12.2 | 18.07,31.24 C17.2 | 20.19,31.24 20.32,31.37 C11.2 | 22.69,31.37 C18.2 23.03,31.24 | v21.59,31.5 21.59,31.37 | C19.2 27.43,32.04 | 27.43,28.57 v27.56,28.57 27.43,28.45 | 27.43,29.5 C21.2 | 27.43,26.16 v27.56,26.16 | 27.43,26.96 C22.2 | 27.43,24.42 C13.2 | C20.2 27.05,22.1 26.92,22.23 | 21.46,23.24 21.59,23.11 | v19.05,23.62 19.05,23.24 | 17.69,23.24 17.82,23.24 C15.2 17.69,23.24 | 17.69,23.24 17.53,23.11 | 18.92,26.04 v18.8,26.04 | 19.05,31.37 18.92,31.24 | 23.37,38.48 23.5,38.12 23.24,38.12 | v9.14,51.69 9.13,51.45 | R27.1 50.38,35.27 50.42,34.92 | 39.41,38.95 C9.2 | 39.41,38.95 39.59,38.95 39.37,38.99 39.5,38.73 39.41,38.95 | v41.02,38.1 41.15,37.85 41.15,36.83 41.91,36.07 41.91,35.3 | QG1.2 8.89,23.74 9.21,24.07 9.34,24.07 9.91,24.89 9.53,23.88 | 14.86,16.76 C8.2 | IC1.1 35.32,2.4 35.69,3.05 | IC6.7 11.56,6.86 | 10.79,5.08 IC8.4 | 17.78,5.21 IC7.4 | 18.41,6.13 C10.2 18.2,6.64 IC5.7 | 51.31,18.41 DEV.M1 51.39,18.49 | IC4.1 27.3,37.85 27.3,38.48 27.05,38.73 25.65,38.73 25.4,38.48 IC4.4 25.4,37.08 25.15,36.83 23.62,36.83 23.37,37.08 23.37,37.72
  Bottom 0.127: 24.77,43.43 24.64,43.56 | 24.64,43.56 IC4.10 24.77,43.43 | IC4.13 26.67,43.56 26.67,44.58 26.04,45.21 25.27,45.21 24.64,44.58 24.64,43.56 | 41.02,41.66 IC10.1 | 41.15,41.91 41.27,40.64 | 43.18,41.91 IC10.4 | 45.34,41.63 45.34,41.78 | 24.77,43.43 24.77,42.8 24.13,42.16 v23.5,42.16 | 23.37,38.48 23.37,37.72 | 23.37,38.48 IC4.7 23.37,37.72 | J1.2 42.55,11.81 | 51.31,27.36 DEV.M2 | 23.24,38.48 23.37,38.48
  Bottom 0.61: v46.48,40.39 46.1,40.77 45.47,40.77 45.45,41.51 | 18.92,27.6 18.92,29.84 18.92,31.24 | 18.92,25.06 18.92,26.04 18.92,27.3 | v19.05,23.62 19.05,24.77 | 20.32,23.24 19.05,23.24 17.82,23.24 | 20.45,23.24 21.46,23.24 22.69,23.24 | 18.92,31.24 18.07,31.24 | 18.92,31.24 20.19,31.24 | 20.45,31.24 21.59,31.24 | 20.45,31.24 20.45,31.37 | 20.32,31.37 20.45,31.24 | 21.59,31.37 21.59,31.24 | 21.59,31.24 22.73,31.24 22.69,31.37 | v24.13,32 24.13,31.24 23.03,31.24 | 27.43,32.04 v27.43,31.11 27.43,29.5 27.43,28.57 | 26.92,22.23 26.92,23.5 v27.43,23.5 27.43,24.42 27.43,26.16 27.43,26.96 27.43,28.45 | C20.2 v26.04,22.1 | 21.59,23.11 v21.59,22.61 | v26.04,32.64 26.29,32.38 C19.2 | v19.05,31.88 19.05,31.37 | v41.02,38.1 41.02,38.73 | v18.41,8.26 IC5.7 | v11.43,8.26 IC6.7 11.43,5.71 10.79,5.08 | 17.78,5.21 18.41,5.84 18.41,6.13 | 41.02,38.73 41.02,41.66 | 41.02,38.73 39.5,38.73 | 45.34,41.78 44.96,42.16 43.05,42.16 | 43.05,42.16 43.18,41.91 | 43.05,42.16 41.4,42.16 41.15,41.91 | 22.86,38.48 23.24,38.12 | 22.86,38.48 23.24,38.48 | v22.73,38.48 22.86,38.48
  Bottom 1.016: R16.1 39.41,27.3 HOST.4 | 46.99,21.46 46.99,21.72 | 46.61,19.18 46.61,20.83 | HOST.P$2 45.18,27.31 | HOST.P$1 45.2,18.43 | 50.42,34.92 50.42,33.11 DIGITAL.20 | 9.91,24.89 v9.91,25.4 v9.91,26.92 | v14.86,17.53 14.86,16.76 | v36.7,3.05 35.69,3.05 | v49.53,18.54 51.31,18.54 51.39,18.49 | v49.53,27.43 51.31,27.43 51.31,27.36
  Bottom 1.27: 9.13,51.45 IC2.1
  pour Top (isolate 0.254): 52.7,52.7 52.7,0.64 0.64,0.64 0.64,52.7
CN3_IN  (via drill 0.3)
  Top 0.127: v31.75,31.62 31.75,31.75 30.73,31.75 IC3.97 | v33.15,34.67 36.07,37.59 36.07,44.96 JP1.2
  Bottom 0.127: R24.2 36.7,48.26 JP1.2 | v31.75,31.62 31.75,33.27 v33.15,34.67
CN3_POW5
  Bottom 0.127: 6.99,27.94 R11.1 6.86,28.07 6.1,28.45
  Bottom 1.778: CN3.20 5.08,28.45 6.1,28.45
CN3_RXD  (via drill 0.3)
  Top 0.127: v34.42,25.15 34.42,24.64 33.66,23.88 33.27,23.88 32.89,24.26 30.73,24.26 IC3.82
  Bottom 0.127: v34.42,25.15 34.42,25.91 34.04,26.29 33.27,26.29 32.13,25.15 32.13,21.97 32.64,21.46 32.64,18.8 30.61,16.76 29.21,16.76 26.54,14.1 26.54,10.03 SERIAL.2
CN3_TXD  (via drill 0.3)
  Top 0.127: v32.38,28.83 31.88,28.32 30.73,28.32 IC3.90
  Bottom 0.127: v32.38,28.83 31.88,28.32 31.88,21.84 32.38,21.34 32.38,18.92 30.48,17.02 29.08,17.02 26.29,14.22 26.29,12.32 SERIAL.1
CSO_B  (via drill 0.3)
  Top 0.127: v13.97,33.66 13.97,33.15 14.35,32.77 IC3.27 | v15.49,13.34 15.88,13.72 18.8,13.72 20.19,15.11 v20.95,15.11
  Bottom 0.127: IC7.1 21.59,9.27 20.95,9.91 IC5.4 v20.95,15.11 | v15.49,13.34 15.49,14.48 14.73,15.24 12.19,15.24 11.68,15.75 11.68,19.81 12.06,20.19 12.06,20.95 11.56,21.46 11.43,21.46 11.05,21.84 11.05,22.35 12.06,23.37 12.06,26.29 13.72,27.94 13.72,28.7 14.61,29.59 14.61,32.38 13.97,33.02 v13.97,33.66
D0  (via drill 0.3)
  Top 0.127: v16.51,18.41 16.76,18.67 16.76,19.05 IC3.51
  Bottom 0.127: IC5.8 17.14,7.87 18.41,9.14 | 18.41,9.14 18.67,8.89 20.07,8.89 20.32,8.64 IC7.2 | 18.41,9.14 18.41,11.94 18.16,12.19 17.91,12.19 17.78,12.32 17.78,14.61 17.53,14.86 17.53,17.4 v16.51,18.41
DE0_1  (via drill 0.3)
  Top 0.127: DE0.2 DE0.1 SP3.1 2.54,65.53 1.4,66.67 1.4,68.07 4.06,70.74 9.53,70.74 11.56,72.77 v11.56,73.41 11.56,74.59 REV.3
  Bottom 0.127: REV.3 11.57,74.03 v11.56,73.41
DE0_3  (via drill 0.3)
  Top 0.127: DE0.4 DE0.3 3.68,61.09 3.68,66.17 SP3.2 2.54,67.82 5.21,70.48 11.05,70.48 v13.46,72.9 13.46,73.66 13.59,73.79 13.59,74.6 REV.7
  Bottom 0.127: 13.57,73.77 REV.7 | 13.57,73.77 13.59,73.79 | 13.57,73.77 13.46,73.66 v13.46,72.9
DE0_3V3  (via drill 0.3)
  Top 0.127: v28.57,73.41 REV.37 | REV.38 29.07,74.05 29.08,73.91 v28.57,73.41 | v29.97,73.41 29.59,73.79 REV.39 | REV.40 30.07,74.01 29.97,73.91 v29.97,73.41 | v29.97,73.41 v28.57,73.41 | v29.97,73.41 33.91,69.47 37.59,69.47 39.37,67.69 39.37,60.96 DE0.29
  Bottom 0.127: REV.37 28.57,73.92 28.57,73.91 v28.57,73.41 29.08,73.91 29.07,73.93 REV.38 | REV.39 29.59,73.79 v29.97,73.41 29.97,73.91 30.1,74.04 REV.40
  Bottom 0.61: SP3.19 27.81,62.36 35.43,62.36 DE0.29
  pour Top (isolate 0.254): 0.64,79.38 0.64,53.98 52.7,53.98 52.7,79.38
DE0_4  (via drill 0.3)
  Top 0.127: DE0.5 5.08,62.23 SP3.3 5.08,65.66 3.94,66.8 3.94,68.07 6.1,70.23 11.81,70.23 14.1,72.52 v14.1,73.41 14.1,74.61 REV.8
  Bottom 0.127: REV.8 14.07,74.01 14.1,74.04 v14.1,73.41
DE0_5  (via drill 0.3)
  Top 0.127: DE0.6 8.76,58.29 8.76,60.07 6.22,62.61 6.22,66.17 SP3.4 5.08,67.82 7.24,69.98 12.19,69.98 14.73,72.52 v14.73,72.9 14.73,73.79 14.61,73.91 14.61,74.61 REV.9
  Bottom 0.127: REV.9 14.57,74.01 14.73,73.79 v14.73,72.9
DE0_5V
  Bottom 0.406: 24.13,62.87 24.13,66.04
  Bottom 0.61: DE0.11 15.24,60.2 16.51,61.47 22.61,61.47 24.13,62.87 | 24.13,66.04 SP3.20
DE0_6  (via drill 0.3)
  Top 0.127: DE0.7 7.62,62.23 SP3.5 7.62,65.53 6.35,66.8 6.35,67.94 8.13,69.72 12.45,69.72 15.37,72.64 v15.37,73.41 15.37,73.53 15.62,73.79 15.62,74.63 REV.11
  Bottom 0.127: REV.11 15.57,73.71 15.37,73.53 v15.37,73.41
DE0_7  (via drill 0.3)
  Top 0.127: DE0.8 11.3,58.29 11.3,60.07 8.76,62.61 8.76,66.17 SP3.6 7.62,67.94 9.14,69.47 12.83,69.47 16,72.64 v16,72.9 16,73.91 16.07,73.98 REV.12
  Bottom 0.127: REV.12 16.07,73.98 16,73.91 v16,72.9
DE0_8  (via drill 0.3)
  Top 0.127: DE0.9 10.16,62.23 SP3.7 10.16,65.53 9.02,66.67 9.02,68.07 10.16,69.22 13.34,69.22 16.64,72.52 v16.64,73.41 16.64,73.91 16.57,73.98 REV.13
  Bottom 0.127: REV.13 16.57,73.97 16.64,73.91 v16.64,73.41
DE0_9  (via drill 0.3)
  Top 0.127: DE0.10 13.84,58.29 13.84,60.07 11.3,62.61 11.3,66.17 SP3.8 10.16,68.07 11.05,68.96 14.1,68.96 17.4,72.26 v17.4,72.9 17.4,73.66 17.57,73.83 REV.15
  Bottom 0.127: REV.15 17.57,73.87 17.53,73.79 17.4,73.66 v17.4,72.9
DE0_10  (via drill 0.3)
  Top 0.127: DE0.13 15.24,62.23 SP3.11 14.1,65.91 14.1,68.2 18.03,72.14 v18.03,73.41 18.03,73.91 18.07,73.95 REV.16
  Bottom 0.127: v18.03,73.41 18.03,74.54 REV.16
DE0_11  (via drill 0.3)
  Top 0.127: DE0.14 18.92,58.29 18.92,60.07 16.38,62.61 16.38,66.17 SP3.12 15.24,68.83 18.67,72.26 v18.67,72.9 18.67,73.79 18.57,73.89 REV.17
  Bottom 0.127: v18.67,72.9 18.67,73.79 18.54,73.91 18.54,74.55 REV.17
DE0_12  (via drill 0.3)
  Top 0.127: DE0.15 17.78,62.23 SP3.13 17.78,65.79 16.51,67.06 16.51,69.34 19.43,72.26 v19.43,73.41 19.57,73.55 REV.19
  Bottom 0.127: v19.43,73.41 19.56,73.53 19.56,74.57 REV.19
DE0_13  (via drill 0.3)
  Top 0.127: DE0.16 21.46,58.29 21.46,60.07 18.92,62.61 18.92,66.17 SP3.14 17.78,69.98 20.07,72.26 v20.07,72.9 20.07,73.66 REV.20
  Bottom 0.127: v20.07,72.9 REV.20
DE0_14  (via drill 0.3)
  Top 0.127: DE0.17 20.32,62.23 SP3.15 20.32,65.79 18.92,67.18 18.92,70.48 20.7,72.26 v20.7,73.41 20.57,73.54 REV.21
  Bottom 0.127: v20.7,73.41 20.57,73.53 REV.21
DE0_15  (via drill 0.3)
  Top 0.127: DE0.18 24,58.29 24,60.07 21.46,62.61 21.46,66.17 SP3.16 20.32,71.12 21.46,72.26 v21.46,72.9 21.46,73.79 21.59,73.91 21.57,73.93 LCD.18
  Bottom 0.127: v21.46,72.9 21.46,73.79 21.59,73.91 21.59,74.56 LCD.18
DE0_16  (via drill 0.3)
  Top 0.127: DE0.19 22.86,62.23 SP3.17 22.86,65.79 21.59,67.06 21.59,71.63 22.1,72.14 v22.1,73.41 22.1,73.66 22.07,73.69 LCD.17
  Bottom 0.127: v22.1,73.41 22.1,74.55 LCD.17
DE0_17  (via drill 0.3)
  Top 0.127: DE0.20 26.54,58.29 26.54,60.07 24,62.61 24,66.17 SP3.18 22.61,67.56 22.61,72.77 v22.73,72.9 22.73,73.79 22.57,73.95 LCD.16
  Bottom 0.127: v22.73,72.9 22.73,73.79 22.61,73.91 22.61,74.54 LCD.16
DE0_18  (via drill 0.3)
  Top 0.127: DE0.21 SP3.21 26.8,65.91 26.8,68.83 23.5,72.14 v23.5,73.41 23.62,73.66 23.57,73.71 LCD.14
  Bottom 0.127: v23.5,73.41 23.62,73.66 23.62,74.53 LCD.14
DE0_19  (via drill 0.3)
  Top 0.127: DE0.22 29.08,58.29 29.08,66.17 SP3.22 27.94,68.33 24.13,72.14 v24.13,72.77 24.13,73.66 24.07,73.72 LCD.13
  Bottom 0.127: v24.13,72.77 24.13,73.66 24.07,73.72 LCD.13
DE0_20  (via drill 0.3)
  Top 0.127: DE0.23 SP3.23 30.48,65.79 29.21,67.06 29.21,67.69 24.77,72.14 v24.77,73.41 24.77,73.53 24.57,73.72 LCD.12
  Bottom 0.127: SP3.23 30.48,64.9 | LCD.12 24.57,73.79 24.77,73.59 v24.77,73.41
DE0_21  (via drill 0.3)
  Top 0.127: DE0.24 31.62,58.29 31.62,66.17 SP3.24 25.53,72.26 v25.53,72.77 25.53,73.66 25.57,73.7 LCD.10
  Bottom 0.127: v25.53,72.77 25.53,74.54 LCD.10
DE0_22  (via drill 0.3)
  Top 0.127: DE0.25 SP3.25 33.02,65.79 31.62,67.18 31.62,67.82 26.54,72.9 v26.54,73.41 26.54,73.66 26.57,73.69 LCD.8
  Bottom 0.127: v26.54,73.41 26.54,74.55 LCD.8
DE0_23  (via drill 0.3)
  Top 0.127: DE0.26 34.16,58.29 34.16,66.17 SP3.26 v27.56,72.77 27.56,73.66 27.57,73.67 LCD.6
  Bottom 0.127: v27.56,72.77 LCD.6
DE0_24
  Top 0.127: DE0.27 SP3.27
DE0_25
  Top 0.127: DE0.28 36.7,58.29 36.7,66.17 SP3.28
DE0_26
  Top 0.127: DE0.31 SP3.31
DE0_27
  Top 0.127: DE0.32 41.78,58.29 41.78,66.17 SP3.32
DE0_28
  Top 0.127: DE0.33 SP3.33
DE0_29
  Top 0.127: DE0.34 44.32,58.29 44.32,66.17 SP3.34
DE0_30
  Top 0.127: DE0.35 SP3.35
DE0_31
  Top 0.127: DE0.36 46.86,58.29 46.86,66.17 SP3.36
DE0_32
  Top 0.127: DE0.37 SP3.37
DE0_33
  Top 0.127: DE0.38 49.4,58.29 49.4,66.17 SP3.38
DE0_34
  Top 0.127: DE0.39 SP3.39
DE0_35
  Top 0.127: DE0.40 51.94,58.29 51.94,66.17 SP3.40
DE0_GND  (via drill 0.3)
  Top 0.127: REV.2 11.07,75.54 v10.92,75.69 10.54,75.31 10.57,75.16 REV.1 | 12.07,75.43 REV.4 | 12.07,75.43 12.06,75.18 | 12.07,75.43 v12.32,75.68 v12.32,75.69 12.57,75.44 REV.5 | REV.10 15.07,75.65 v15.11,75.69 | REV.14 17.07,75.39 17.02,75.44 v17.02,75.69 | REV.18 19.07,75.67 v19.05,75.69 | v21.08,75.69 21.08,74.59 REV.22 | v23.11,75.69 23.11,75.31 23.07,75.27 REV.26 | v25.02,75.69 25.02,74.63 REV.30 | REV.32 26.07,75.66 v26.04,75.69
  Bottom 0.127: REV.1 10.57,75.34 v10.92,75.69 | v12.32,75.69 12.06,75.44 REV.4 12.07,75.44 v12.32,75.69 | v12.32,75.69 v12.32,75.7 | 12.57,75.44 REV.5 | 12.57,75.44 12.36,75.65 | 15.07,75.65 REV.10 | 15.07,75.65 v15.11,75.69 v17.02,75.69 | 17.07,74.6 17.07,75.26 17.02,75.44 v17.02,75.69 | REV.22 v21.07,75.68 v21.08,75.69 | REV.26 23.07,75.27 23.11,75.31 v23.11,75.69 | v25.02,75.69 25.02,75.31 25.07,75.26 REV.30 25.07,75.62 25.15,75.69 v26.04,75.69 | v26.04,75.69 26.04,75.56 | REV.32 26.04,74.61 26.04,75.56 | DE0.30 39.37,58.42 39.37,63.5 SP3.29 SP3.30 38.1,77.22 36.7,78.61 27.81,78.61 26.04,76.83 | DE0.12 13.97,58.42 13.97,63.5 SP3.9 SP3.10 12.57,67.44 12.57,75.44 | 12.36,75.65 15.07,75.65 | 12.36,75.65 v12.32,75.69 | v19.05,75.69 v21.08,75.69 | v21.08,75.69 v23.11,75.69 | v23.11,75.69 v25.02,75.69 | 26.04,76.83 v26.04,75.69 | v25.02,75.69 26.04,76.83 | v12.32,75.69 v10.92,75.69 | REV.18 19.07,75.67 v19.05,75.69 | v17.02,75.69 v19.05,75.69 | v17.02,75.69 17.02,75.18 | 17.07,74.6 REV.14 | 17.02,75.18 17.07,74.6 | 17.02,75.18 17.02,74.68 | v26.04,75.69 26.16,75.56 26.04,75.56 | REV.2 11.07,75.54 v10.92,75.69
  pour Bottom (isolate 0.254): 0.64,79.38 0.64,53.98 52.7,53.98 52.7,79.38
DONE  (via drill 0.3)
  Top 0.127: v8.64,14.73 9.14,14.73 10.92,16.51 17.02,16.51 18.41,17.91 18.41,19.43 IC3.54 | v8.64,7.62 8.89,7.62 9.91,6.6 R14.2 9.53,6.35
  Bottom 0.127: v8.64,7.62 v8.64,14.73
HPD1  (via drill 0.3)
  Top 0.127: DIGITAL.19 43.88,36.39 43.69,36.2 43.69,35.43 43.81,35.31 v43.81,33.27
  Bottom 0.127: v43.81,33.27 43.81,33.66 44.45,34.29 44.45,35.17 IC10.9 44.45,35.23 44.45,36.45 44.83,36.83 47.12,36.83 48.39,35.56 R27.2
INIT_B  (via drill 0.3)
  Top 0.127: v11.18,20.57 12.7,20.57 14.48,22.35 14.99,22.35 IC3.48
  Bottom 0.127: IC8.2 13.34,8.51 12.7,9.14 | 10.16,6.73 IC6.8 10.16,7.87 11.18,8.89 12.45,8.89 12.7,9.14 | v11.18,20.57 11.18,15.37 12.06,14.48 12.06,12.45 12.32,12.19 12.45,12.19 12.7,11.94 12.7,9.14
MOSI  (via drill 0.3)
  Top 0.127: v11.68,22.1 12.95,23.37 14.48,23.37 14.54,23.3 IC3.46
  Bottom 0.127: IC7.5 17.91,11.05 17.91,11.56 17.14,12.32 IC5.1 17.14,14.22 15.88,15.49 12.32,15.49 11.94,15.88 11.94,19.68 12.32,20.07 12.32,21.46 v11.68,22.1
N$2
  Bottom 0.127: R19.2 38.23,14.86 | 40.26,19.27 HOST.1
  Bottom 1.016: 38.23,14.86 39.62,14.86 40.26,15.49 40.26,19.27
N$4
  Bottom 0.127: R20.2 38.1,21.21 38.23,21.34 39.83,21.34 HOST.2
N$5
  Bottom 0.127: R21.2 38.1,23.37 38.23,23.5 39.98,23.5 HOST.3
N$6
  Bottom 0.127: DEV.2 43.34,23.66 42.93,23.24 42.58,23.24 R22.2
N$9
  Bottom 0.127: DEV.3 43.69,22.86 42.93,22.1 42.58,21.97 R23.2
N$10
  Bottom 0.127: R6.1 32.6,12.91 LED1.A
POW3  (via drill 0.3)
  Top 0.127: 31.92,7.96 C3.1 | 29.21,7.24 C2.1
  Top 1.016: v33.15,6.48 32.13,7.49 | 32.13,7.49 31.92,7.71 31.92,7.96 | 29.21,7.24 31.88,7.24 32.13,7.49
  Bottom 0.127: 33.15,8.74 IC1.4 32.79,8.64 31.75,8.64 31.37,8.76 | v33.15,6.48 33.02,6.35 | R1.1 28.19,4.7
  Bottom 1.778: 28.19,4.7 31.37,4.7 31.37,6.35
  Bottom 2.54: 33.02,6.35 IC1.2
  Bottom 5.08: 33.15,8.74 v33.15,6.48 | 31.37,6.35 31.37,8.76
PROG_B
  Top 0.127: IC3.100 30.73,33.4 31.62,33.4 32.51,34.29 32.51,36.83 R7.1 32.64,36.83 32.64,39.5 IC9.2
SCL1  (via drill 0.3)
  Top 0.127: DIGITAL.15 44.23,38.39 43.69,38.35 43.43,38.35 42.93,37.85 v42.55,37.85
  Bottom 0.127: IC10.3 42.55,40.98 42.55,39.75 41.91,39.12 41.91,38.23 42.29,37.85 v42.55,37.85 42.93,37.85 43.43,38.35 47.37,38.35 47.88,38.86 47.88,40.01 48.13,40.26 48.3,40.26 R26.1
SDA1  (via drill 0.3)
  Top 0.127: DIGITAL.16 43.86,37.89 43.81,37.85 43.43,37.85 42.67,37.08 42.67,36.45 v42.8,36.32
  Bottom 0.127: 42.55,35.34 42.55,34.67 | 42.55,35.34 42.55,36.07 v42.8,36.32 42.67,36.45 42.67,37.08 43.69,38.1 R25.1 | IC10.12 42.55,35.34
TCK  (via drill 0.3)
  Top 0.127: v27.94,36.7 27.3,36.7 23.5,40.51 23.11,40.51 21.59,42.04 JTAG.1
  Bottom 0.127: 18.92,42.29 19.05,42.42 R2.1 19.18,42.29 18.92,42.29 | JTAG.1 19.94,46.99 17.91,44.96 17.91,43.31 18.92,42.29 | IC4.2 26.67,37.72 26.67,37.08 27.05,36.7 v27.94,36.7
TDI
  Bottom 0.127: 32.89,42.29 32,43.18 32,46.99 JTAG.9 | 32.89,42.29 32.89,40.51 31.37,38.99 25.02,38.99 24.77,38.73 24.77,37.85 IC4.5 | 32.89,42.29 32.89,42.42 R5.1 33.02,42.04
TDO  (via drill 0.3)
  Top 0.127: v25.53,44.58 25.53,45.59 JTAG.3
  Bottom 0.127: v25.53,44.58 25.4,44.45 IC4.11
TMS
  Bottom 0.127: R4.1 30.48,42.29 29.59,43.18 29.59,44.07 JTAG.5 24.13,44.45 24.13,43.56 IC4.9
VCCINT  (via drill 0.3)
  Top 0.127: 12.7,48.6 C4.1 | IC3.17 20.86,34 v21.59,33.27 | IC3.38 16.51,27.3 | IC3.66 24.36,21.23 v24.13,21.46 | IC3.81 29.9,23.8 28.96,24.77
  Top 1.016: 16.51,27.3 17.27,27.3 17.27,28.19 v17.65,28.57 | 24.13,22.73 v24.13,21.46 | 22.73,28.57 22.73,32.13 v21.59,33.27 | v28.96,26.04 28.96,24.77 25.91,24.89
  Top 1.27: v11.43,47.24 11.43,48.64 12.7,48.6 | C4.1 C5.1
  Top 2.54: v17.65,28.57 22.73,28.57 24.13,27.18 24.13,24.89 | 24.13,24.89 24.13,22.73 | 24.13,24.89 25.91,24.89
  Bottom 0.127: 20.36,33.27 C11.1 | 17.27,27.77 C14.1 17.27,27.3 | 22.95,21.46 C12.1 | 28.96,24.77 28.57,24.55 C13.1
  Bottom 0.61: v24.13,21.46 22.95,21.46
  Bottom 1.016: 20.36,33.27 v21.59,33.27 21.59,34.29 | v17.65,28.57 17.27,28.19 17.27,27.77 | v28.96,26.04 28.96,24.77
  Bottom 1.27: IC2.4 11.43,42.42 12.7,41.15 16.76,41.15 21.59,36.32 21.59,34.29
  Bottom 1.778: 11.43,47.37 IC2.2
  Bottom 3.81: IC2.4 v11.43,47.24 11.43,47.37
XCE  (via drill 0.3)
  Top 0.127: IC3.29 14.55,31.8 14.48,31.75 14.1,31.75 v13.46,32.38
  Bottom 0.127: R8.1 12.7,33.27 v13.46,32.38 14.35,31.5 14.35,29.72 13.46,28.83 13.46,28.07 11.81,26.42 11.81,23.5 10.79,22.48 10.79,21.72 11.3,21.21 11.43,21.21 11.81,20.83 11.81,20.32 11.43,19.94 11.43,15.62 12.06,14.99 13.08,14.99 13.97,14.1 IC6.4 13.97,9.78 14.61,9.14 IC8.1
XCK  (via drill 0.3)
  Top 0.127: v13.46,31.37 14.35,31.37 14.41,31.3 IC3.30
  Bottom 0.127: 12.7,31.37 12.7,31.24 R9.1 12.57,31.11 12.7,31.37 | IC8.6 12.06,11.94 11.43,12.57 IC6.2 11.43,14.73 10.92,15.24 10.92,19.94 10.54,20.32 10.54,22.61 11.56,23.62 11.56,26.54 13.21,28.19 13.21,28.96 14.1,29.84 14.1,30.73 v13.46,31.37 12.7,31.37
XDI  (via drill 0.3)
  Top 0.127: v13.46,30.23 13.84,30.23 14.41,30.8 IC3.31
  Bottom 0.127: 12.57,28.96 13.46,29.84 v13.46,30.23 | IC8.5 10.79,11.81 10.16,12.45 IC6.1 10.16,16.26 8.38,18.03 8.38,20.83 11.3,23.75 11.3,26.67 12.57,27.94 12.57,28.96 | 12.57,28.96 12.32,28.83 R10.1
XTCK  (via drill 0.3)
  Top 0.127: v30.61,20.57 30.61,21.21 30.73,21.21 IC3.76 | v30.61,34.67 30.35,34.67 29.72,35.31 v29.72,36.45
  Bottom 0.127: v30.61,20.57 v30.61,34.67 | v29.72,36.45 29.34,36.07 26.92,36.07 25.91,37.08 26.04,37.85 IC4.3
XTDI  (via drill 0.3)
  Top 0.127: v25.53,39.62 25.53,38.86 27.05,37.34 28.19,37.34 28.57,36.96 28.57,35.94 28.32,35.69 28.32,35.18 IC3.2
  Bottom 0.127: v25.53,39.62 25.27,39.62 24.13,38.48 24.13,37.85 IC4.6
XTDO  (via drill 0.3)
  Top 0.127: v29.21,20.95 29.21,19.81 28.96,19.56 IC3.75 | v29.72,34.42 29.46,34.67 29.46,35.56 29.08,35.94 29.08,37.21 28.45,37.85 27.3,37.85 27.05,38.1 v27.05,39.62
  Bottom 0.127: v29.21,20.95 30.35,22.1 30.35,33.78 v29.72,34.42 | v27.05,39.62 27.05,40.26 26.29,41.02 26.29,42.16 26.04,42.42 | 26.04,42.42 24.77,42.42 24.13,41.78 24.13,40.89 23.75,40.51 23.11,40.51 22.1,41.53 22.1,42.16 21.59,42.16 R3.1 | 26.04,43.43 26.04,43.69 | 26.04,42.42 26.04,43.43 | 26.04,43.43 IC4.12
XTMS  (via drill 0.3)
  Top 0.127: v23.37,41.15 24.26,40.26 25.91,40.26 26.29,39.88 26.29,38.48 27.18,37.59 28.32,37.59 28.83,37.08 28.83,35.18 IC3.1
  Bottom 0.127: v23.37,41.15 22.86,41.66 22.86,42.55 23.37,43.05 23.37,43.43 IC4.8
